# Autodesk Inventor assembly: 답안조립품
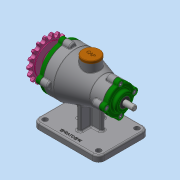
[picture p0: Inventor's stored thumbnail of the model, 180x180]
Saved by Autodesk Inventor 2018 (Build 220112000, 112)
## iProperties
Created: 2020-12
Part Number: 답안조립품
Material: 일반
Document SubType Name: Assembly
Designer: home
Author: home
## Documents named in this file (15)
- C:\Users\home\Desktop\701206V1022\답안조립품.iam
- C:\Users\home\Desktop\701206V1022\본체.ipt
- C:\Users\home\Desktop\701206V1022\앞커버.ipt
- C:\Users\home\Desktop\701206V1022\뒤커버.ipt
- C:\Users\home\Desktop\701206V1022\개스킷 B.ipt
- C:\Users\home\Desktop\701206V1022\개스킷 A.ipt
- C:\Users\home\Desktop\701206V1022\볼트 M5.ipt
- C:\Users\home\Desktop\701206V1022\오일 실 10 20 7.ipt
- C:\Users\home\Desktop\701206V1022\오일 실 17 30 8.ipt
- C:\Users\home\Desktop\701206V1022\베어링 6200.ipt
- C:\Users\home\Desktop\701206V1022\베어링 6203.ipt
- C:\Users\home\Desktop\701206V1022\축.ipt
- C:\Users\home\Desktop\701206V1022\키 4x4x14.ipt
- C:\Users\home\Desktop\701206V1022\스프로킷.ipt
- C:\Users\home\Desktop\701206V1022\마개.ipt
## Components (2 placed, 2 different names)
1. 개스킷 B:1
2. 개스킷 A:1
